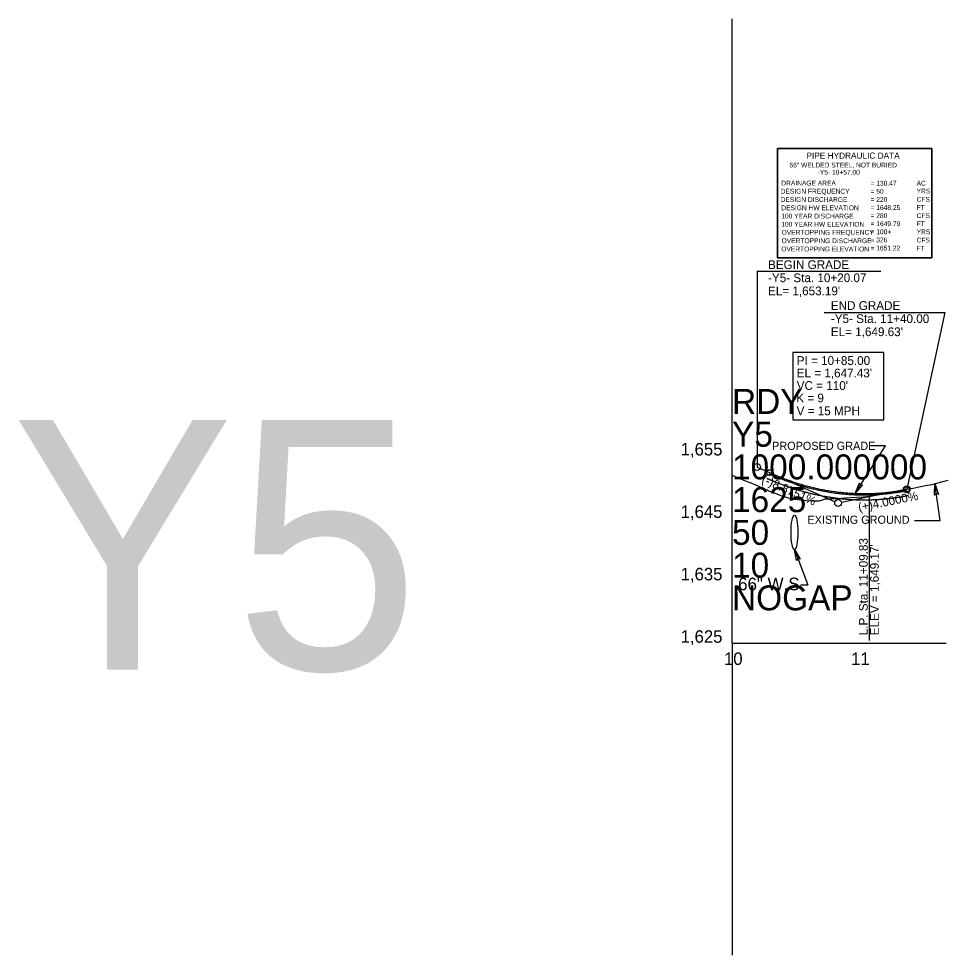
# Model space of a CAD drawing. Extents: x 498575 to 532350, y 405181 to 484585.
# Drawn here: x 505285 to 506030, y 462668 to 463418 of the extents above; entities that cross this region are included whole.
import ezdxf

# ---------------------------------------------------------------- set-up
doc = ezdxf.new("R2010")
doc.units = 0
for name, color, linetype in [('Exist Profile Cell', 7, 'Continuous'), ('Exist Vertical Profile Ground Line', 7, 'Continuous'), ('Exist Vertical Profile Horizontal Axis Label Major', 7, 'Continuous'), ('Exist Vertical Profile Vertical Axis Label', 7, 'Continuous'), ('Prop Drainage Structure Pipe Welded Steel 54in Label', 7, 'Continuous'), ('Prop Grid Mask', 7, 'Continuous'), ('Prop PFL Text', 7, 'Continuous'), ('Prop Vertical Profile Curve Label', 7, 'Continuous'), ('Prop Vertical Profile Grade', 7, 'Continuous'), ('Prop Vertical Profile Grade Label', 7, 'Continuous'), ('Prop Vertical Profile Strip Grade', 7, 'Continuous'), ('Prop VPI Label', 7, 'Continuous'), ('Scratch_Level_5', 7, 'Continuous'), ('Scratch_Level_7', 7, 'Continuous'), ('Sheet Data Text CELL', 7, 'Continuous')]:
    doc.layers.add(name, color=color, linetype=linetype)

msp = doc.modelspace()

# ---------------------------------------------------------------- linework, layer by layer
at = {"layer": 'Exist Profile Cell'}
for q in [(505856.74, 463418.37), (506028.23, 462918.37), (505856.74, 462668.37)]:
    msp.add_line((505856.74, 462918.37), q, dxfattribs=at)
at = {"layer": 'Exist Vertical Profile Ground Line'}
msp.add_lwpolyline([(505856.74, 463052.84), (505861.74, 463050.72), (505866.74, 463048.71), (505871.74, 463046.77), (505876.74, 463044.5), (505881.74, 463042.43), (505886.74, 463040.01), (505891.74, 463038.09), (505896.74, 463036.28), (505901.74, 463034.74), (505906.74, 463033.74), (505911.74, 463033.1), (505916.74, 463032.49), (505921.74, 463032.24), (505926.74, 463032.18), (505931.74, 463033.89), (505936.74, 463033.99), (505941.74, 463034.29), (505946.74, 463034.59), (505951.74, 463034.9), (505956.74, 463035.2), (505961.74, 463035.5), (505966.74, 463036.01), (505971.74, 463036.72), (505976.74, 463037.66), (505981.74, 463038.61), (505986.74, 463039.56), (505991.74, 463040.5), (505996.74, 463041.51), (506001.74, 463042.5), (506006.74, 463043.49), (506011.74, 463044.47), (506016.74, 463045.44), (506021.74, 463046.71), (506026.74, 463048), (506029.95, 463048.83)], dxfattribs=at)
at = {"layer": 'Prop Drainage Structure Pipe Welded Steel 54in Label'}
for p in [(505906.74, 462993.37), (505911.5, 462965.05)]:
    msp.add_line(p, (505917.45, 462965.05), dxfattribs=at)
msp.add_lwpolyline([(505908.47, 462984.41), (505906.74, 462993.37), (505911.44, 462985.47), (505909.53, 462985.98)], close=True, dxfattribs=at)
msp.add_ellipse((505906.74, 463007.12), major_axis=(0, 13.75), ratio=0.2, dxfattribs=at)
at = {"layer": 'Prop Grid Mask'}
for points in [[(505893.12, 463314.47), (506016.87, 463314.47), (506016.87, 463227.02), (505893.12, 463227.02)], [(505905.38, 463097.12), (505978.39, 463097.12), (505978.39, 463151.07), (505905.38, 463151.07)]]:
    msp.add_lwpolyline(points, close=True, dxfattribs=at)
at = {"layer": 'Prop PFL Text'}
for p, q in [((505955.32, 463038.24), (505979.76, 463076.38)), ((505979.76, 463076.38), (505968.05, 463076.38)), ((506023.37, 463016.46), (506019.24, 463046.07)), ((506003, 463016.46), (506023.37, 463016.46))]:
    msp.add_line(p, q, dxfattribs=at)
for points in [[(505961.43, 463045.03), (505955.32, 463038.24), (505958.79, 463046.75), (505959.53, 463044.93)], [(506018.95, 463036.95), (506019.24, 463046.07), (506022.08, 463037.33), (506020.33, 463038.25)]]:
    msp.add_lwpolyline(points, close=True, dxfattribs=at)
at = {"layer": 'Prop Vertical Profile Curve Label'}
for centre in [(505886.74, 463054.92), (505996.74, 463041.51)]:
    msp.add_circle(centre, 2.25, dxfattribs=at)
at = {"layer": 'Prop Vertical Profile Grade'}
msp.add_line((505876.81, 463059.32), (505886.74, 463054.92), dxfattribs=at)
msp.add_spline([(505886.74, 463054.92), (505888.94, 463053.95), (505891.14, 463053.02), (505893.34, 463052.11), (505895.54, 463051.24), (505897.74, 463050.39), (505899.94, 463049.57), (505902.14, 463048.78), (505904.34, 463048.01), (505906.54, 463047.28), (505908.74, 463046.57), (505910.94, 463045.89), (505913.14, 463045.24), (505915.34, 463044.62), (505917.54, 463044.02), (505919.74, 463043.46), (505921.94, 463042.92), (505924.14, 463042.41), (505926.34, 463041.93), (505928.54, 463041.48), (505930.74, 463041.06), (505932.94, 463040.66), (505935.14, 463040.29), (505937.34, 463039.95), (505939.54, 463039.64), (505941.74, 463039.36), (505943.94, 463039.11), (505946.14, 463038.88), (505948.34, 463038.68), (505950.54, 463038.51), (505952.74, 463038.37), (505954.94, 463038.26), (505957.14, 463038.18), (505959.34, 463038.12), (505961.54, 463038.09), (505963.74, 463038.1), (505965.94, 463038.12), (505968.14, 463038.18), (505970.34, 463038.27), (505972.54, 463038.38), (505974.74, 463038.52), (505976.94, 463038.7), (505979.14, 463038.9), (505981.34, 463039.12), (505983.54, 463039.38), (505985.74, 463039.66), (505987.94, 463039.98), (505990.14, 463040.32), (505992.34, 463040.69), (505994.54, 463041.08), (505996.74, 463041.51)], degree=3, dxfattribs=at)
at = {"layer": 'Prop Vertical Profile Strip Grade'}
for p, q in [((505966.46, 463038.14), (505966.46, 463021.22)), ((505966.46, 463026.17), (505966.46, 462920.35))]:
    msp.add_line(p, q, dxfattribs=at)
at = {"layer": 'Prop VPI Label'}
for p, q in [((505876.82, 463216.35), (505876.81, 463059.32)), ((505876.82, 463216.35), (505976, 463216.35)), ((505930.64, 463183.11), (506027.21, 463183.11)), ((506027.21, 463183.11), (505996.74, 463041.51)), ((505886.74, 463054.92), (505939.23, 463031.62)), ((505996.74, 463041.51), (505944.44, 463031.05))]:
    msp.add_line(p, q, dxfattribs=at)
for centre in [(505876.81, 463059.32), (505996.74, 463041.51), (505941.74, 463030.51)]:
    msp.add_circle(centre, 2.75, dxfattribs=at)
at = {"layer": 'Scratch_Level_5'}
for points in [[(505884.74, 463050.33), (505885.27, 463050.1), (505885.95, 463049.81), (505886.65, 463049.5), (505886.84, 463049.42), (505886.9, 463049.39), (505886.92, 463049.38), (505886.93, 463049.37), (505886.94, 463049.37), (505886.94, 463049.37), (505886.95, 463049.37), (505887.02, 463049.33), (505887.1, 463049.3), (505887.46, 463049.15), (505887.74, 463049.03), (505888.3, 463048.79), (505888.58, 463048.67), (505888.92, 463048.53), (505888.99, 463048.5), (505889.09, 463048.46), (505889.14, 463048.44), (505889.19, 463048.42), (505889.21, 463048.4), (505889.22, 463048.4), (505889.24, 463048.39), (505889.39, 463048.33), (505890.09, 463048.04), (505891.34, 463047.53), (505892.45, 463047.08), (505893.29, 463046.75), (505893.57, 463046.64), (505894.13, 463046.42), (505895.53, 463045.88), (505896.93, 463045.35), (505898.34, 463044.83), (505898.63, 463044.72), (505899.19, 463044.52), (505900.04, 463044.21), (505900.89, 463043.91), (505902.02, 463043.52), (505902.59, 463043.32), (505903.73, 463042.94), (505904.87, 463042.56), (505906.02, 463042.19), (505906.88, 463041.91), (505907.16, 463041.82), (505907.74, 463041.64), (505908.6, 463041.37), (505909.75, 463041.02), (505910.62, 463040.77), (505911.19, 463040.6), (505911.48, 463040.51), (505912.93, 463040.1), (505914.09, 463039.77), (505915.54, 463039.38), (505915.83, 463039.3), (505916.42, 463039.15), (505916.71, 463039.07), (505917.58, 463038.85), (505918.75, 463038.55), (505919.92, 463038.26), (505921.09, 463037.98), (505921.68, 463037.84), (505923.44, 463037.44), (505924.62, 463037.18), (505926.98, 463036.69), (505928.16, 463036.45), (505929.94, 463036.12), (505930.53, 463036.01), (505931.72, 463035.8), (505932.31, 463035.69), (505933.5, 463035.49), (505934.1, 463035.39), (505935.29, 463035.21), (505936.48, 463035.02), (505937.68, 463034.85), (505938.87, 463034.69), (505939.47, 463034.61), (505941.27, 463034.38), (505942.46, 463034.24), (505944.86, 463033.98), (505946.07, 463033.86), (505948.47, 463033.65), (505949.68, 463033.56), (505952.09, 463033.4), (505953.29, 463033.33), (505956.91, 463033.17), (505959.33, 463033.1), (505964.16, 463033.08), (505966.57, 463033.12), (505970.19, 463033.25), (505971.4, 463033.31), (505973.81, 463033.45), (505975.02, 463033.53), (505976.82, 463033.67), (505977.42, 463033.72), (505978.63, 463033.82), (505979.23, 463033.88), (505981.03, 463034.06), (505982.23, 463034.19), (505984.63, 463034.47), (505985.82, 463034.63), (505987.62, 463034.87), (505988.21, 463034.96), (505989.41, 463035.14), (505990.6, 463035.32), (505991.79, 463035.52), (505992.53, 463035.64), (505992.76, 463035.68), (505993.02, 463035.73), (505993.14, 463035.75), (505993.18, 463035.76), (505993.2, 463035.76), (505993.21, 463035.76), (505993.24, 463035.77), (505993.26, 463035.77), (505993.56, 463035.82), (505993.86, 463035.87), (505994.46, 463035.98), (505994.76, 463036.04), (505995.15, 463036.11), (505995.22, 463036.12), (505995.34, 463036.14), (505995.4, 463036.16), (505995.46, 463036.17), (505995.48, 463036.17), (505995.49, 463036.17), (505995.49, 463036.17), (505995.5, 463036.18), (505995.51, 463036.18), (505995.67, 463036.21), (505996.39, 463036.35), (505997.11, 463036.49), (505997.69, 463036.6)], [(505886.32, 463053.96), (505886.86, 463053.73), (505887.53, 463053.43), (505888.24, 463053.12), (505888.42, 463053.04), (505888.48, 463053.02), (505888.51, 463053.01), (505888.52, 463053), (505888.53, 463052.99), (505888.61, 463052.96), (505888.68, 463052.93), (505889.02, 463052.78), (505889.29, 463052.67), (505889.83, 463052.44), (505890.11, 463052.32), (505890.44, 463052.18), (505890.51, 463052.15), (505890.65, 463052.1), (505890.72, 463052.07), (505890.92, 463051.98), (505891.6, 463051.7), (505892.28, 463051.42), (505893.92, 463050.75), (505895.02, 463050.32), (505897.22, 463049.47), (505898.32, 463049.05), (505900.53, 463048.24), (505901.64, 463047.84), (505903.87, 463047.07), (505904.99, 463046.69), (505907.23, 463045.95), (505908.35, 463045.59), (505910.61, 463044.9), (505911.74, 463044.56), (505914.01, 463043.9), (505915.14, 463043.59), (505917.42, 463042.97), (505918.56, 463042.68), (505920.85, 463042.11), (505922, 463041.83), (505924.3, 463041.3), (505925.45, 463041.05), (505927.76, 463040.57), (505928.92, 463040.34), (505931.24, 463039.9), (505932.4, 463039.69), (505934.73, 463039.3), (505935.9, 463039.11), (505938.23, 463038.77), (505939.4, 463038.61), (505942.91, 463038.16), (505945.26, 463037.9), (505949.96, 463037.5), (505952.32, 463037.34), (505955.86, 463037.18), (505957.04, 463037.13), (505959.4, 463037.07), (505960.58, 463037.06), (505964.12, 463037.04), (505966.48, 463037.08), (505971.2, 463037.25), (505973.56, 463037.38), (505977.09, 463037.66), (505978.27, 463037.76), (505980.62, 463037.99), (505981.79, 463038.12), (505984.13, 463038.4), (505985.3, 463038.55), (505987.64, 463038.87), (505988.81, 463039.05), (505990.56, 463039.33), (505991.29, 463039.45), (505992.09, 463039.58), (505992.34, 463039.63), (505992.45, 463039.65), (505992.52, 463039.66), (505992.56, 463039.67), (505992.88, 463039.72), (505993.17, 463039.77), (505993.76, 463039.88), (505994.05, 463039.93), (505994.41, 463040), (505994.52, 463040.02), (505994.65, 463040.04), (505994.71, 463040.05), (505994.74, 463040.06), (505994.76, 463040.06), (505994.92, 463040.1), (505995.64, 463040.24), (505996.36, 463040.37), (505996.94, 463040.49)]]:
    msp.add_open_spline(points, degree=3, dxfattribs=at)
at = {"layer": 'Sheet Data Text CELL'}
msp.add_lwpolyline([(505893.12, 463227.02), (506016.87, 463227.02), (506016.87, 463314.47), (505893.12, 463314.47)], close=True, dxfattribs=at)

# ---------------------------------------------------------------- texts
at = {"layer": 'Exist Profile Cell'}
for s, p in [('RDY', (505856.74, 463101.9)), ('Y5', (505856.74, 463075.68)), ('1000.000000', (505856.74, 463049.47)), ('1625', (505856.74, 463023.25)), ('50', (505856.74, 462997.03)), ('10', (505856.74, 462970.81)), ('NOGAP', (505856.74, 462944.59))]:
    msp.add_text(s, height=20, dxfattribs=at).set_placement(p)
at = {"layer": 'Exist Vertical Profile Horizontal Axis Label Major'}
for s, p in [('10', (505850.32, 462900.87)), ('11', (505952.16, 462900.87))]:
    msp.add_text(s, height=10, dxfattribs=at).set_placement(p)
at = {"layer": 'Exist Vertical Profile Vertical Axis Label'}
for s, p in [('1,655', (505815.59, 463068.62)), ('1,645', (505815.59, 463018.62)), ('1,635', (505815.59, 462968.62)), ('1,625', (505815.59, 462918.62))]:
    msp.add_text(s, height=10, dxfattribs=at).set_placement(p)
at = {"layer": 'Prop Drainage Structure Pipe Welded Steel 54in Label'}
msp.add_text('66" W.S', height=10.125, dxfattribs=at).set_placement((505861.63, 462960.67))
at = {"layer": 'Prop PFL Text'}
for s, p in [('PROPOSED GRADE', (505888.8, 463073.09)), ('EXISTING GROUND', (505917.13, 463013.91))]:
    msp.add_text(s, height=6.5157, dxfattribs=at).set_placement(p)
at = {"layer": 'Prop Vertical Profile Curve Label'}
for s, p in [("VC = 110'", (505908.56, 463121.16)), ('K = 9', (505908.2, 463111.18))]:
    msp.add_text(s, height=7, dxfattribs=at).set_placement(p)
at = {"layer": 'Prop Vertical Profile Grade Label'}
for s, rotation, p in [('(-)8.8751%', 336.07051, (505879.86, 463047.03)), ('(+)4.0000%', 11.30993, (505958.55, 463023.67))]:
    msp.add_text(s, height=7, rotation=rotation, dxfattribs=at).set_placement(p)
at = {"layer": 'Prop Vertical Profile Strip Grade'}
for s, p in [('L.P. Sta. 11+09.83', (505965.44, 462924.67)), ("ELEV = 1,649.17'", (505974.31, 462924.67))]:
    msp.add_text(s, height=7, rotation=90, dxfattribs=at).set_placement(p)
at = {"layer": 'Prop VPI Label'}
for s, p in [('BEGIN GRADE', (505885.57, 463217.91)), ('-Y5- Sta. 10+20.07', (505885.57, 463207.41)), ("EL= 1,653.19'", (505885.57, 463196.91)), ('END GRADE', (505935.88, 463185.19)), ('-Y5- Sta. 11+40.00', (505935.88, 463174.69)), ("EL= 1,649.63'", (505935.88, 463164.19)), ('PI = 10+85.00', (505908.56, 463141.16)), ("EL = 1,647.43'", (505908.56, 463131.16)), ('V = 15 MPH', (505908.48, 463100.86))]:
    msp.add_text(s, height=7, dxfattribs=at).set_placement(p)
at = {"layer": 'Scratch_Level_7'}
msp.add_text('Y5', height=200, dxfattribs=at).set_placement((505279.5, 462897.03))
at = {"layer": 'Sheet Data Text CELL'}
for s, height, p in [('PIPE HYDRAULIC DATA', 4.9498, (505916.38, 463306.28)), ('DRAINAGE AREA', 3.8499, (505896.19, 463284.83)), ('= 130.47', 3.85, (505967.7, 463284.72)), ('AC', 3.85, (506004.58, 463284.72)), ('DESIGN FREQUENCY', 3.8499, (505895.69, 463278.31)), ('DESIGN DISCHARGE', 3.8499, (505895.69, 463271.63)), ('= 50', 3.85, (505967.7, 463278.23)), ('= 220', 3.85, (505967.7, 463271.74)), ('YRS', 3.85, (506004.58, 463278.45)), ('CFS', 3.85, (506004.58, 463271.82)), ('DESIGN HW ELEVATION', 3.8499, (505896.19, 463265.03)), ('FT', 3.85, (506004.58, 463265.25)), ('100 YEAR DISCHARGE', 3.8499, (505896.19, 463258.43)), ('= 280', 3.85, (505967.7, 463258.76)), ('CFS', 3.85, (506004.58, 463258.76)), ('100 YEAR HW ELEVATION', 3.8499, (505896.19, 463251.83)), ('FT', 3.85, (506004.58, 463252.27)), ('OVERTOPPING FREQUENCY', 3.8499, (505896.43, 463245.39)), ('= 100+', 3.85, (505967.7, 463245.78)), ('YRS', 3.85, (506004.58, 463245.83)), ('OVERTOPPING DISCHARGE', 3.8499, (505896.43, 463238.65)), ('CFS', 3.85, (506004.58, 463239.2)), ('OVERTOPPING ELEVATION', 3.8499, (505896.19, 463232.03)), ('= 1651.22', 3.85, (505967.7, 463232.8)), ('FT', 3.85, (506004.58, 463232.58))]:
    msp.add_text(s, height=height, rotation=360, dxfattribs=at).set_placement(p)
for s, p in [('66" WELDED STEEL, NOT BURIED', (505902.75, 463299.26)), ('   -Y5- 10+57.00', (505920.84, 463293.48)), ('= 1648.25', (505967.7, 463265.25)), ('= 1649.79', (505967.7, 463252.27)), ('= 326', (505967.7, 463239.29))]:
    msp.add_text(s, height=3.85, dxfattribs=at).set_placement(p)

doc.saveas('drawing.dxf')
